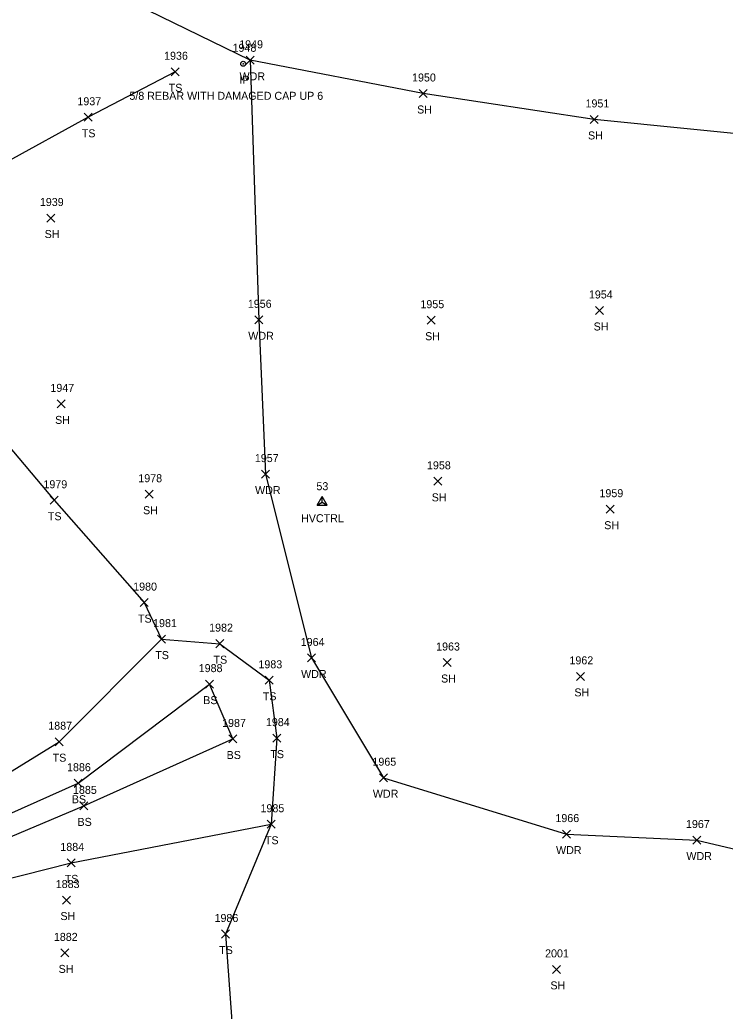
# Model space of a CAD drawing. Extents: x 1754529 to 1755810, y 621660 to 624656.
# Drawn here: x 1755244.8 to 1755421.2, y 624086.9 to 624334.6 of the extents above; entities that cross this region are included whole.
import ezdxf

# ---------------------------------------------------------------- set-up
doc = ezdxf.new("R2010")
doc.units = 0
for name, color, linetype in [('C_A', 7, 'Continuous'), ('C_I', 7, 'Continuous'), ('CPSM', 7, 'Continuous'), ('L_A', 7, 'Continuous'), ('L_I', 7, 'Continuous'), ('L_TIC', 7, 'Continuous'), ('LAWA', 7, 'Continuous'), ('LELB', 7, 'Continuous'), ('LSOGP', 7, 'Continuous'), ('M_A', 7, 'Continuous'), ('M_C', 7, 'Continuous'), ('M_I', 7, 'Continuous'), ('MPIR', 7, 'Continuous')]:
    doc.layers.add(name, color=color, linetype=linetype)

msp = doc.modelspace()

# ---------------------------------------------------------------- linework, layer by layer
at = {"layer": 'CPSM'}
for p, q in [((1755319.18, 624213.31), (1755320.43, 624215.48)), ((1755319.18, 624213.31), (1755320.43, 624214.03)), ((1755319.18, 624213.31), (1755321.68, 624213.31)), ((1755321.68, 624213.31), (1755320.43, 624215.48)), ((1755320.43, 624214.03), (1755320.43, 624215.48)), ((1755320.43, 624214.03), (1755320.43, 624214.03)), ((1755320.43, 624214.03), (1755321.68, 624213.31))]:
    msp.add_line(p, q, dxfattribs=at)
at = {"layer": 'L_TIC'}
for points in [[(1755301.36, 624323.44), (1755303.36, 624325.44)], [(1755303.36, 624323.44), (1755301.36, 624325.44)], [(1755282.63, 624320.58), (1755284.63, 624322.58)], [(1755284.63, 624320.58), (1755282.63, 624322.58)], [(1755344.65, 624315.15), (1755346.65, 624317.15)], [(1755346.65, 624315.15), (1755344.65, 624317.15)], [(1755260.89, 624309.21), (1755262.89, 624311.21)], [(1755262.89, 624309.21), (1755260.89, 624311.21)], [(1755387.37, 624308.67), (1755389.37, 624310.67)], [(1755389.37, 624308.67), (1755387.37, 624310.67)], [(1755251.52, 624284.04), (1755253.52, 624286.04)], [(1755253.52, 624284.04), (1755251.52, 624286.04)], [(1755388.77, 624260.94), (1755390.77, 624262.94)], [(1755390.77, 624260.94), (1755388.77, 624262.94)], [(1755303.56, 624258.61), (1755305.56, 624260.61)], [(1755305.56, 624258.61), (1755303.56, 624260.61)], [(1755346.65, 624258.51), (1755348.65, 624260.51)], [(1755348.65, 624258.51), (1755346.65, 624260.51)], [(1755254.14, 624237.6), (1755256.14, 624239.6)], [(1755256.14, 624237.6), (1755254.14, 624239.6)], [(1755305.26, 624220.06), (1755307.26, 624222.06)], [(1755307.26, 624220.06), (1755305.26, 624222.06)], [(1755348.29, 624218.25), (1755350.29, 624220.25)], [(1755350.29, 624218.25), (1755348.29, 624220.25)], [(1755252.41, 624213.52), (1755254.41, 624215.52)], [(1755254.41, 624213.52), (1755252.41, 624215.52)], [(1755276.12, 624215.03), (1755278.12, 624217.03)], [(1755278.12, 624215.03), (1755276.12, 624217.03)], [(1755391.42, 624211.29), (1755393.42, 624213.29)], [(1755393.42, 624211.29), (1755391.42, 624213.29)], [(1755274.93, 624187.95), (1755276.93, 624189.95)], [(1755276.93, 624187.95), (1755274.93, 624189.95)], [(1755279.26, 624178.83), (1755281.26, 624180.83)], [(1755281.26, 624178.83), (1755279.26, 624180.83)], [(1755279.26, 624178.83), (1755281.26, 624180.83)], [(1755281.26, 624178.83), (1755279.26, 624180.83)], [(1755293.83, 624177.69), (1755295.83, 624179.69)], [(1755295.83, 624177.69), (1755293.83, 624179.69)], [(1755316.77, 624174.11), (1755318.77, 624176.11)], [(1755318.77, 624174.11), (1755316.77, 624176.11)], [(1755350.63, 624172.98), (1755352.63, 624174.98)], [(1755352.63, 624172.98), (1755350.63, 624174.98)], [(1755383.96, 624169.52), (1755385.96, 624171.52)], [(1755385.96, 624169.52), (1755383.96, 624171.52)], [(1755291.22, 624167.58), (1755293.22, 624169.58)], [(1755293.22, 624167.58), (1755291.22, 624169.58)], [(1755291.22, 624167.58), (1755293.22, 624169.58)], [(1755293.22, 624167.58), (1755291.22, 624169.58)], [(1755306.15, 624168.54), (1755308.15, 624170.54)], [(1755308.15, 624168.54), (1755306.15, 624170.54)], [(1755308.03, 624154.09), (1755310.03, 624156.09)], [(1755310.03, 624154.09), (1755308.03, 624156.09)], [(1755253.61, 624153.2), (1755255.61, 624155.2)], [(1755255.61, 624153.2), (1755253.61, 624155.2)], [(1755297.07, 624153.88), (1755299.07, 624155.88)], [(1755299.07, 624153.88), (1755297.07, 624155.88)], [(1755334.71, 624144.2), (1755336.71, 624146.2)], [(1755336.71, 624144.2), (1755334.71, 624146.2)], [(1755258.36, 624142.82), (1755260.36, 624144.82)], [(1755260.36, 624142.82), (1755258.36, 624144.82)], [(1755259.79, 624137.16), (1755261.79, 624139.16)], [(1755261.79, 624137.16), (1755259.79, 624139.16)], [(1755306.67, 624132.57), (1755308.67, 624134.57)], [(1755308.67, 624132.57), (1755306.67, 624134.57)], [(1755306.67, 624132.57), (1755308.67, 624134.57)], [(1755308.67, 624132.57), (1755306.67, 624134.57)], [(1755380.51, 624130.11), (1755382.51, 624132.11)], [(1755382.51, 624130.11), (1755380.51, 624132.11)], [(1755413.09, 624128.63), (1755415.09, 624130.63)], [(1755415.09, 624128.63), (1755413.09, 624130.63)], [(1755256.64, 624122.92), (1755258.64, 624124.92)], [(1755258.64, 624122.92), (1755256.64, 624124.92)], [(1755255.48, 624113.63), (1755257.48, 624115.63)], [(1755257.48, 624113.63), (1755255.48, 624115.63)], [(1755295.24, 624105.15), (1755297.24, 624107.15)], [(1755297.24, 624105.15), (1755295.24, 624107.15)], [(1755255.02, 624100.43), (1755257.02, 624102.43)], [(1755257.02, 624100.43), (1755255.02, 624102.43)], [(1755377.98, 624096.31), (1755379.98, 624098.31)], [(1755379.98, 624096.31), (1755377.98, 624098.31)]]:
    msp.add_lwpolyline(points, dxfattribs=at)
at = {"layer": 'LAWA'}
msp.add_lwpolyline([(1755302.36, 624324.44), (1755304.56, 624259.61), (1755306.26, 624221.06), (1755317.77, 624175.11), (1755335.71, 624145.2), (1755381.51, 624131.11), (1755414.09, 624129.63), (1755447.66, 624121.7), (1755477.75, 624119.95), (1755506.85, 624141.45), (1755530.35, 624173.06), (1755521.71, 624132.68), (1755513.72, 624106.64), (1755499.73, 624051.71), (1755491.49, 624010.7), (1755483.31, 623982.28), (1755477.84, 623954.98), (1755471.72, 623930.68), (1755463.31, 623898.52), (1755457.13, 623867.77), (1755453.48, 623847.93), (1755451.28, 623827.38), (1755449.92, 623802.26), (1755447.47, 623775.96)], dxfattribs=at)
at = {"layer": 'LELB'}
for points in [[(1755283.63, 624321.58), (1755261.89, 624310.21), (1755241.28, 624298.92), (1755225.63, 624290.24), (1755219.57, 624277.64), (1755236.29, 624268.09), (1755239.17, 624251.56), (1755235.61, 624235.54), (1755253.41, 624214.52), (1755275.93, 624188.95), (1755280.26, 624179.83), (1755294.83, 624178.69), (1755307.15, 624169.54), (1755309.03, 624155.09), (1755307.67, 624133.57), (1755296.24, 624106.15), (1755299.26, 624064.9), (1755318.78, 624037.89), (1755344, 624017.13), (1755370, 623994.13), (1755389.34, 623965.32), (1755402.54, 623944.92), (1755412.5, 623921.31), (1755426.67, 623899.96)], [(1755224.52, 624135.71), (1755254.61, 624154.2), (1755280.26, 624179.83)], [(1755217.55, 624125.18), (1755259.36, 624143.82), (1755292.22, 624168.58)], [(1755218.11, 624120.19), (1755260.79, 624138.16), (1755298.07, 624154.88), (1755292.22, 624168.58)], [(1755213.31, 624113.19), (1755221.73, 624114.88), (1755257.64, 624123.92), (1755307.67, 624133.57)]]:
    msp.add_lwpolyline(points, dxfattribs=at)
at = {"layer": 'LSOGP'}
msp.add_lwpolyline([(1755437.36, 624304.76), (1755388.37, 624309.67), (1755345.65, 624316.15), (1755302.36, 624324.44), (1755245.19, 624352.34)], dxfattribs=at)
at = {"layer": 'MPIR'}
for radius in [0.625, 0.0833]:
    msp.add_circle((1755300.68, 624323.57), radius, dxfattribs=at)

# ---------------------------------------------------------------- texts
at = {"layer": 'C_A'}
msp.add_text('HVCTRL', height=2, dxfattribs=at).set_placement((1755315.12, 624209.03))
at = {"layer": 'C_I'}
msp.add_text('53', height=2, dxfattribs=at).set_placement((1755318.96, 624217.03))
at = {"layer": 'L_A'}
for s, p in [('WDR', (1755299.73, 624319.44)), ('TS', (1755282.03, 624316.58)), ('SH', (1755344.14, 624311.15)), ('TS', (1755260.3, 624305.21)), ('SH', (1755386.86, 624304.67)), ('SH', (1755251.01, 624280.04)), ('SH', (1755388.26, 624256.94)), ('WDR', (1755301.92, 624254.61)), ('SH', (1755346.14, 624254.51)), ('SH', (1755253.63, 624233.6)), ('WDR', (1755303.62, 624216.06)), ('SH', (1755347.78, 624214.25)), ('SH', (1755275.61, 624211.03)), ('TS', (1755251.82, 624209.52)), ('SH', (1755390.91, 624207.29)), ('TS', (1755274.34, 624183.95)), ('TS', (1755278.67, 624174.83)), ('TS', (1755278.67, 624174.83)), ('TS', (1755293.24, 624173.69)), ('WDR', (1755315.13, 624170.11)), ('SH', (1755350.12, 624168.98)), ('TS', (1755305.56, 624164.54)), ('SH', (1755383.45, 624165.52)), ('BS', (1755290.66, 624163.58)), ('BS', (1755290.66, 624163.58)), ('TS', (1755253.02, 624149.2)), ('BS', (1755296.51, 624149.88)), ('TS', (1755307.44, 624150.09)), ('WDR', (1755333.07, 624140.2)), ('BS', (1755257.8, 624138.82)), ('BS', (1755259.23, 624133.16)), ('TS', (1755306.08, 624128.57)), ('TS', (1755306.08, 624128.57)), ('WDR', (1755378.87, 624126.11)), ('WDR', (1755411.45, 624124.63)), ('TS', (1755256.04, 624118.92)), ('SH', (1755254.97, 624109.63)), ('TS', (1755294.65, 624101.15)), ('SH', (1755254.51, 624096.43)), ('SH', (1755377.46, 624092.31))]:
    msp.add_text(s, height=2, dxfattribs=at).set_placement(p)
at = {"layer": 'L_I'}
for s, p in [('1949', (1755299.66, 624327.44)), ('1936', (1755280.88, 624324.58)), ('1950', (1755342.87, 624319.15)), ('1937', (1755259.2, 624313.21)), ('1951', (1755386.24, 624312.67)), ('1939', (1755249.82, 624288.04)), ('1954', (1755387.08, 624264.94)), ('1956', (1755301.81, 624262.61)), ('1955', (1755344.96, 624262.51)), ('1947', (1755252.45, 624241.6)), ('1957', (1755303.57, 624224.06)), ('1958', (1755346.6, 624222.25)), ('1978', (1755274.43, 624219.03)), ('1979', (1755250.71, 624217.52)), ('1959', (1755389.72, 624215.29)), ('1980', (1755273.15, 624191.95)), ('1981', (1755278.13, 624182.83)), ('1981', (1755278.13, 624182.83)), ('1982', (1755292.14, 624181.69)), ('1964', (1755315.03, 624178.11)), ('1963', (1755348.89, 624176.98)), ('1988', (1755289.53, 624171.58)), ('1988', (1755289.53, 624171.58)), ('1983', (1755304.46, 624172.54)), ('1962', (1755382.22, 624173.52)), ('1887', (1755251.92, 624157.2)), ('1987', (1755295.38, 624157.88)), ('1984', (1755306.33, 624158.09)), ('1886', (1755256.61, 624146.82)), ('1965', (1755332.97, 624148.2)), ('1885', (1755258.1, 624141.16)), ('1985', (1755304.98, 624136.57)), ('1985', (1755304.98, 624136.57)), ('1966', (1755378.71, 624134.11)), ('1967', (1755411.35, 624132.63)), ('1884', (1755254.94, 624126.92)), ('1883', (1755253.79, 624117.63)), ('1986', (1755293.49, 624109.15)), ('1882', (1755253.32, 624104.43)), ('2001', (1755376.13, 624100.31))]:
    msp.add_text(s, height=2, dxfattribs=at).set_placement(p)
at = {"layer": 'M_A'}
msp.add_text('IP', height=2, dxfattribs=at).set_placement((1755299.73, 624318.57))
at = {"layer": 'M_C'}
msp.add_text('5/8 REBAR WITH DAMAGED CAP UP 6', height=2, dxfattribs=at).set_placement((1755272.2, 624314.57))
at = {"layer": 'M_I'}
msp.add_text('1948', height=2, dxfattribs=at).set_placement((1755297.99, 624326.57))

doc.saveas('drawing.dxf')
